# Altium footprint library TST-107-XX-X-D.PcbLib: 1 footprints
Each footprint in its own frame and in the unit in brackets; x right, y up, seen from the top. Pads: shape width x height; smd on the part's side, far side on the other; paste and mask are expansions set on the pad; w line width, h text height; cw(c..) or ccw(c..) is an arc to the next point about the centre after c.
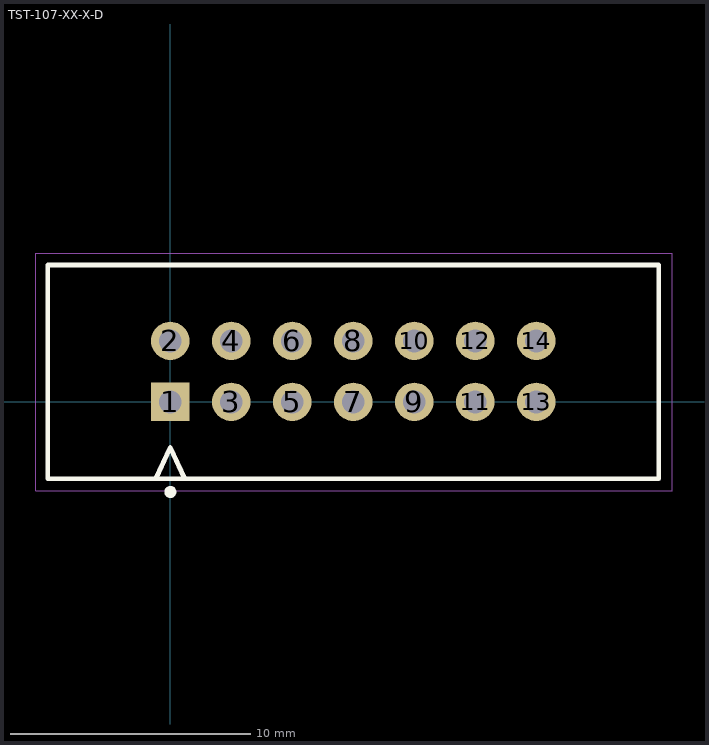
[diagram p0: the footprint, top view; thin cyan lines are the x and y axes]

## TST-107-XX-X-D [mm] "2.54mm pitch, 14 pin, header; shrouded"
height 8.89
pads (14):
  rect 1.6x1.6 / inner round 1.6 / far side rect 1.6x1.6 hole 0.95 mask+0: 1(0,0)
  round 1.6 hole 0.95 mask+0: 2(0,2.54) 3(2.54,0) 4(2.54,2.54) 5(5.08,0) 6(5.08,2.54) 7(7.62,0) 8(7.62,2.54) 9(10.16,0) 10(10.16,2.54) 11(12.7,0) 12(12.7,2.54) 13(15.24,0) 14(15.24,2.54)
Top Overlay:
  circle w0.25: c0,-3.75 r0.125
  lines w0.2: -5.1,-3.2 -5.1,5.7 20.34,5.7 20.34,-3.2 -5.1,-3.2 ; -0.6,-3.2 0.6,-3.2 0,-1.9 -0.6,-3.2
Mechanical 12:
  lines w0.001: -5.1,-3.2 -5.1,5.7 20.34,5.7 20.34,-3.2 -5.1,-3.2
Mechanical 13:
  lines w0.1: -5.1,-3.2 -5.1,5.7 20.34,5.7 20.34,-3.2 -5.1,-3.2 ; -0.6,-3.2 0.6,-3.2 0,-1.9 -0.6,-3.2
  text ".Designator" at 0,0 h1.52
Mechanical 15:
  lines w0.05: -5.6,-3.7 -5.6,6.2 20.9,6.2 20.9,-3.7 -5.6,-3.7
